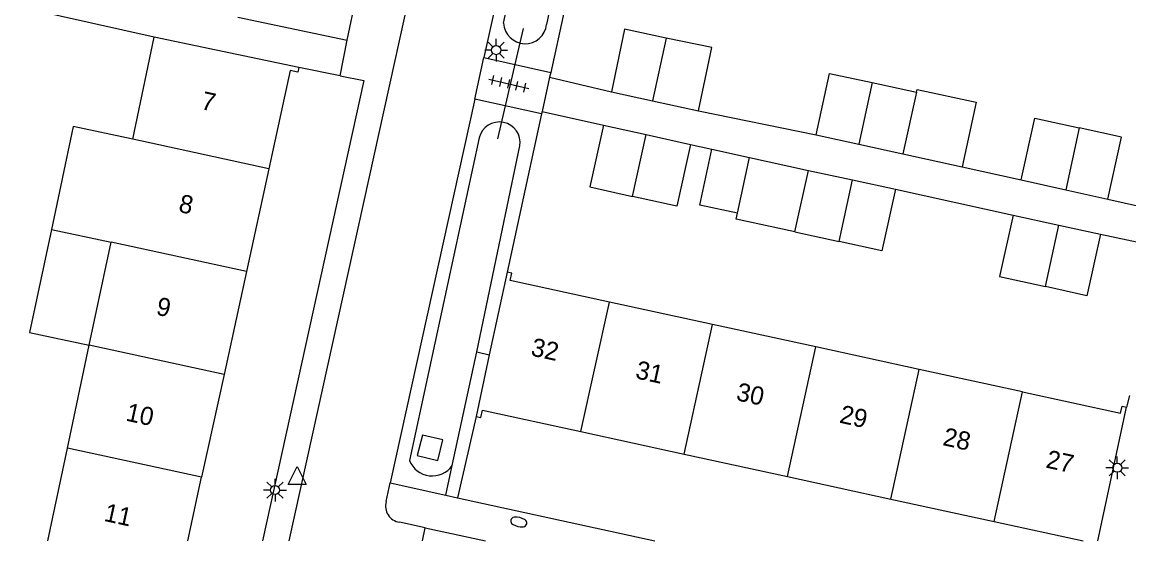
# Model space of a CAD drawing. Extents: x 130998 to 133001, y 398999 to 403002.
# Drawn here: x 131096.8 to 131157.5, y 399000 to 399028.5 of the extents above; entities that cross this region are included whole.
import ezdxf

# ---------------------------------------------------------------- set-up
doc = ezdxf.new("R2010")
doc.units = 0
for name, color, linetype in [('gg-afsc-erfafscheiding', 7, 'Continuous'), ('gg-afsc-muur', 7, 'Continuous'), ('gg-anno-huisnummerreeks BGT', 7, 'Continuous'), ('gg-bbg-bijgebouw', 7, 'Continuous'), ('gg-bbg-gedigitaliseerde bebouwing', 7, 'Continuous'), ('gg-bbg-gedigitaliseerde bijgebouw', 7, 'Continuous'), ('gg-bbg-hoofdgebouw', 7, 'Continuous'), ('gg-bbg-luifel en loopbrug', 7, 'Continuous'), ('gg-bbg-tussenscheiding', 7, 'Continuous'), ('gg-knt-verharding', 7, 'Continuous'), ('gg-knt-verharding nz', 7, 'Continuous'), ('gg-kntw-greppel-droge sloot', 7, 'Continuous'), ('gg-kwrk-duiker nz buis', 7, 'Continuous'), ('gg-kwrk-uitstroombak niveau min 01', 7, 'Continuous'), ('gt-grn-weggrens', 7, 'Continuous'), ('gt-symb-brandkraan', 7, 'Continuous'), ('gt-symb-lichtmast', 7, 'Continuous'), ('gt-symb-tegel verharding', 7, 'Continuous'), ('gt-symb-waterafsluiter', 7, 'Continuous')]:
    doc.layers.add(name, color=color, linetype=linetype)

# ---------------------------------------------------------------- blocks, each defined once
blk = doc.blocks.new('gt0-LMAST')
at = {"layer": 'gt-symb-lichtmast'}
for p, q in [((-0.005, 0.246), (-0.005, 0.621)), ((-0.182, 0.173), (-0.447, 0.438)), ((0.172, 0.173), (0.437, 0.438)), ((-0.255, -0.004), (-0.63, -0.004)), ((-0.182, -0.181), (-0.447, -0.446)), ((-0.005, -0.254), (-0.005, -0.629)), ((0.437, -0.446), (0.172, -0.181)), ((0.245, -0.004), (0.62, -0.004))]:
    blk.add_line(p, q, dxfattribs=at)
blk.add_circle((-0.005, -0.004), 0.25, dxfattribs=at)
blk = doc.blocks.new('gt0-BR')
at = {"layer": 'gt-symb-brandkraan'}
for centre, radius, start, end in [((-0.244, 0), 0.206, 107.56694, 252.43307), ((0.599, -2.664), 3, 106.89205, 107.56694), ((0, -0.691), 0.938, 73.10799, 106.89205), ((-0.599, -2.664), 3, 72.43309, 73.10799), ((0.244, 0), 0.206, 287.56695, 72.43309), ((0.599, 2.664), 3, 252.43307, 253.10797), ((0, 0.691), 0.938, 253.10797, 286.89206), ((-0.599, 2.664), 3, 286.89206, 287.56695)]:
    blk.add_arc(centre, radius, start, end, dxfattribs=at)
blk = doc.blocks.new('gt0-WAFSL')
at = {"layer": 'gt-symb-waterafsluiter'}
for p, q in [((-0.5, -0.333), (0, 0.667)), ((0, 0.667), (0.5, -0.333)), ((0.5, -0.333), (-0.5, -0.333))]:
    blk.add_line(p, q, dxfattribs=at)
blk = doc.blocks.new('gt0-TEG1')
at = {"layer": 'gt-symb-tegel verharding'}
for p, q in [((-1.125, 0), (1.125, 0)), ((-0.9, -0.25), (-0.9, 0.25)), ((-0.45, -0.25), (-0.45, 0.25)), ((0, -0.25), (0, 0.25)), ((0.45, -0.25), (0.45, 0.25)), ((0.9, -0.25), (0.9, 0.25))]:
    blk.add_line(p, q, dxfattribs=at)

msp = doc.modelspace()

# ---------------------------------------------------------------- linework, layer by layer
at = {"layer": 'gg-afsc-erfafscheiding'}
for p, q in [((131104.014, 399027.698), (131094.396, 399029.839)), ((131125.725, 399025.49), (131129.112, 399024.689)), ((131125.316, 399023.614), (131128.678, 399022.859)), ((131133.897, 399023.654), (131140.359, 399022.328)), ((131133.458, 399021.799), (131134.629, 399021.541)), ((131148.375, 399020.565), (131151.626, 399019.851)), ((131144.718, 399019.335), (131151.179, 399017.907)), ((131156.383, 399018.796), (131159.813, 399018.024)), ((131155.968, 399016.861), (131159.359, 399016.139))]:
    msp.add_line(p, q, dxfattribs=at)
at = {"layer": 'gg-afsc-muur'}
for p, q in [((131127.941, 399035.66), (131125.784, 399025.761)), ((131125.784, 399025.761), (131125.725, 399025.49)), ((131125.316, 399023.614), (131125.286, 399023.475)), ((131125.286, 399023.475), (131123.391, 399014.78)), ((131157.56, 399007.999), (131157.412, 399007.348))]:
    msp.add_line(p, q, dxfattribs=at)
at = {"layer": 'gg-bbg-bijgebouw'}
for p, q in [((131114.611, 399027.54), (131115.246, 399030.546)), ((131108.593, 399028.805), (131114.611, 399027.54)), ((131129.112, 399024.689), (131131.366, 399024.202)), ((131131.366, 399024.202), (131133.897, 399023.654)), ((131128.678, 399022.859), (131131.019, 399022.34)), ((131131.019, 399022.34), (131133.458, 399021.799)), ((131140.359, 399022.328), (131142.696, 399021.814)), ((131142.696, 399021.814), (131145.124, 399021.279)), ((131139.94, 399020.372), (131142.36, 399019.847)), ((131142.36, 399019.847), (131144.718, 399019.335)), ((131151.626, 399019.851), (131154.067, 399019.31)), ((131154.067, 399019.31), (131156.383, 399018.796)), ((131151.179, 399017.907), (131153.686, 399017.359)), ((131153.686, 399017.359), (131155.968, 399016.861))]:
    msp.add_line(p, q, dxfattribs=at)
at = {"layer": 'gg-bbg-gedigitaliseerde bebouwing'}
for p, q in [((131102.831, 399022.093), (131104.014, 399027.698)), ((131098.361, 399017.122), (131101.635, 399016.43)), ((131100.44, 399010.766), (131101.635, 399016.43)), ((131129.003, 399013.128), (131123.561, 399014.311)), ((131134.676, 399011.895), (131129.003, 399013.128)), ((131140.35, 399010.662), (131134.676, 399011.895)), ((131099.244, 399005.102), (131100.44, 399010.766)), ((131146.023, 399009.429), (131140.35, 399010.662)), ((131151.695, 399008.196), (131146.023, 399009.429)), ((131098.167, 399000), (131099.244, 399005.102))]:
    msp.add_line(p, q, dxfattribs=at)
for points in [[(131102.831, 399022.093), (131099.557, 399022.785), (131098.361, 399017.122)], [(131151.695, 399008.196), (131157.083, 399007.025), (131157.166, 399007.401), (131157.412, 399007.348)]]:
    msp.add_lwpolyline(points, dxfattribs=at)
at = {"layer": 'gg-bbg-gedigitaliseerde bijgebouw'}
for p, q in [((131143.436, 399025.198), (131145.865, 399024.667)), ((131145.865, 399024.667), (131145.124, 399021.279)), ((131139.196, 399016.998), (131139.94, 399020.372)), ((131139.196, 399016.998), (131141.619, 399016.464))]:
    msp.add_line(p, q, dxfattribs=at)
for points in [[(131132.12, 399027.652), (131129.833, 399028.131), (131129.112, 399024.689)], [(131133.897, 399023.654), (131134.625, 399027.127), (131132.12, 399027.652)], [(131140.359, 399022.328), (131141.098, 399025.709), (131143.436, 399025.198)], [(131151.626, 399019.851), (131152.368, 399023.244), (131154.811, 399022.71)], [(131128.678, 399022.859), (131127.93, 399019.463), (131130.276, 399018.946)], [(131156.383, 399018.796), (131157.128, 399022.203), (131154.811, 399022.71)], [(131133.458, 399021.799), (131132.712, 399018.409), (131130.276, 399018.946)], [(131144.718, 399019.335), (131143.971, 399015.946), (131141.619, 399016.464)], [(131151.179, 399017.907), (131150.437, 399014.538), (131152.948, 399013.985)], [(131155.968, 399016.861), (131155.223, 399013.483), (131152.948, 399013.985)]]:
    msp.add_lwpolyline(points, dxfattribs=at)
at = {"layer": 'gg-bbg-hoofdgebouw'}
for p, q in [((131111.951, 399026.03), (131104.014, 399027.698)), ((131110.306, 399020.465), (131109.074, 399014.809)), ((131109.074, 399014.809), (131107.842, 399009.153)), ((131123.391, 399014.78), (131122.411, 399010.228)), ((131122.411, 399010.228), (131121.681, 399006.84)), ((131107.842, 399009.153), (131106.61, 399003.497)), ((131155.826, 399000), (131157.412, 399007.348)), ((131127.444, 399006.01), (131133.116, 399004.774)), ((131133.116, 399004.774), (131138.789, 399003.538)), ((131105.848, 399000), (131106.61, 399003.497)), ((131138.789, 399003.538), (131144.461, 399002.302)), ((131144.461, 399002.302), (131150.134, 399001.066)), ((131150.134, 399001.066), (131155.026, 399000))]:
    msp.add_line(p, q, dxfattribs=at)
for points in [[(131111.951, 399026.03), (131111.891, 399025.77), (131111.481, 399025.86), (131110.306, 399020.465)], [(131123.561, 399014.311), (131123.651, 399014.72), (131123.391, 399014.78)], [(131121.681, 399006.84), (131121.941, 399006.78), (131122.031, 399007.19), (131127.444, 399006.01)]]:
    msp.add_lwpolyline(points, dxfattribs=at)
at = {"layer": 'gg-bbg-luifel en loopbrug'}
for p, q in [((131134.629, 399021.541), (131136.699, 399021.086)), ((131145.124, 399021.279), (131148.375, 399020.565)), ((131136.043, 399018.021), (131136.699, 399021.086)), ((131136.699, 399021.086), (131139.94, 399020.372))]:
    msp.add_line(p, q, dxfattribs=at)
for points in [[(131145.865, 399024.667), (131145.9, 399024.826), (131149.147, 399024.121), (131148.375, 399020.565)], [(131136.043, 399018.021), (131133.97, 399018.464), (131134.629, 399021.541)], [(131139.196, 399016.998), (131135.972, 399017.688), (131136.043, 399018.021)], [(131098.361, 399017.122), (131097.165, 399011.458), (131100.44, 399010.766)]]:
    msp.add_lwpolyline(points, dxfattribs=at)
at = {"layer": 'gg-bbg-tussenscheiding'}
for p, q in [((131132.12, 399027.652), (131131.366, 399024.202)), ((131143.436, 399025.198), (131142.696, 399021.814)), ((131154.811, 399022.71), (131154.067, 399019.31)), ((131110.306, 399020.465), (131102.831, 399022.093)), ((131130.276, 399018.946), (131131.019, 399022.34)), ((131141.619, 399016.464), (131142.36, 399019.847)), ((131152.948, 399013.985), (131153.686, 399017.359)), ((131109.074, 399014.809), (131101.635, 399016.43)), ((131127.444, 399006.01), (131129.003, 399013.128)), ((131133.116, 399004.774), (131134.676, 399011.895)), ((131107.842, 399009.153), (131100.44, 399010.766)), ((131138.789, 399003.538), (131140.35, 399010.662)), ((131144.461, 399002.302), (131146.023, 399009.429)), ((131150.134, 399001.066), (131151.695, 399008.196)), ((131106.61, 399003.497), (131099.244, 399005.102))]:
    msp.add_line(p, q, dxfattribs=at)
at = {"layer": 'gg-knt-verharding'}
for p, q in [((131125.771, 399043.206), (131122.105, 399026.579)), ((131114.214, 399025.576), (131111.951, 399026.03)), ((131121.608, 399024.281), (131122.105, 399026.579)), ((131122.105, 399026.579), (131125.784, 399025.761)), ((131121.608, 399024.281), (131116.958, 399003.186)), ((131125.286, 399023.475), (131121.608, 399024.281)), ((131120.371, 399004.146), (131121.721, 399010.389)), ((131121.721, 399010.389), (131122.411, 399010.228)), ((131121.681, 399006.84), (131120.669, 399002.368)), ((131120.016, 399002.506), (131120.371, 399004.146)), ((131116.754, 399002.158), (131116.958, 399003.186)), ((131116.958, 399003.186), (131120.016, 399002.506)), ((131120.669, 399002.368), (131131.507, 399000)), ((131118.893, 399000.718), (131117.473, 399001.028)), ((131118.893, 399000.718), (131122.2, 399000))]:
    msp.add_line(p, q, dxfattribs=at)
for points in [[(131111.428, 399000), (131112.694, 399005.809), (131121.161, 399044.215)], [(131114.214, 399025.576), (131115.513, 399025.316), (131109.955, 399000)]]:
    msp.add_lwpolyline(points, dxfattribs=at)
msp.add_arc((131117.593, 399001.898), 0.878, 162.78138, 262.15444, dxfattribs=at)
at = {"layer": 'gg-knt-verharding nz'}
msp.add_line((131118.737, 399000), (131118.893, 399000.718), dxfattribs=at)
at = {"layer": 'gg-kntw-greppel-droge sloot'}
for p, q in [((131121.853, 399022.159), (131118.024, 399004.419)), ((131121.721, 399010.389), (131124.096, 399021.716))]:
    msp.add_line(p, q, dxfattribs=at)
msp.add_lwpolyline([(131123.198, 399028.47), (131125.912, 399041.14), (131128.122, 399040.581), (131125.558, 399028.396)], dxfattribs=at)
for centre, radius, start, end in [((131124.381, 399028.524), 1.184, 182.63552, 353.77253), ((131122.965, 399021.89), 1.144, 351.25592, 166.39944), ((131119.271, 399004.917), 1.343, 201.76747, 324.96302)]:
    msp.add_arc(centre, radius, start, end, dxfattribs=at)
at = {"layer": 'gg-kwrk-duiker nz buis'}
msp.add_line((131124.274, 399028.167), (131122.867, 399022.112), dxfattribs=at)
at = {"layer": 'gg-kwrk-uitstroombak niveau min 01'}
msp.add_lwpolyline([(131118.457, 399004.699), (131119.583, 399004.427), (131119.863, 399005.549), (131118.736, 399005.821), (131118.457, 399004.699)], dxfattribs=at)
at = {"layer": 'gt-grn-weggrens'}
for p, q in [((131114.214, 399025.576), (131114.611, 399027.54)), ((131125.725, 399025.49), (131125.316, 399023.614)), ((131120.016, 399002.506), (131120.669, 399002.368))]:
    msp.add_line(p, q, dxfattribs=at)

# ---------------------------------------------------------------- block references
at = {"layer": 'gt-symb-brandkraan', "rotation": 166.9346126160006}
msp.add_blockref('gt0-BR', (131124.029, 399001.039), dxfattribs=at)
at = {"layer": 'gt-symb-lichtmast'}
for p in [(131122.792, 399026.99), (131156.9, 399004.024), (131110.647, 399002.796)]:
    msp.add_blockref('gt0-LMAST', p, dxfattribs=at)
at = {"layer": 'gt-symb-tegel verharding', "rotation": -13.480126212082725}
msp.add_blockref('gt0-TEG1', (131123.481, 399025.129), dxfattribs=at)
at = {"layer": 'gt-symb-waterafsluiter'}
msp.add_blockref('gt0-WAFSL', (131111.862, 399003.431), dxfattribs=at)

# ---------------------------------------------------------------- texts
at = {"layer": 'gg-anno-huisnummerreeks BGT'}
for s, p in [('7', (131106.53, 399023.754)), ('8', (131105.299, 399018.104)), ('9', (131104.067, 399012.448)), ('32', (131124.643, 399010.203)), ('31', (131130.387, 399008.951)), ('30', (131135.92, 399007.745)), ('10', (131102.401, 399006.622)), ('29', (131141.593, 399006.509)), ('28', (131147.265, 399005.273)), ('27', (131152.927, 399004.039)), ('11', (131101.2, 399001.106))]:
    msp.add_text(s, height=1, rotation=347.7, dxfattribs=at).set_placement(p)

doc.saveas('drawing.dxf')
